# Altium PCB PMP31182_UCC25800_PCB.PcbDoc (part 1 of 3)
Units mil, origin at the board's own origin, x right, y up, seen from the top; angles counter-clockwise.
Board outline 4922 x 2266 mil, 4 copper layers (Top Layer, Signal Layer 1, Signal Layer 2, Bottom Layer), stack 77.9 mil thick; 172 components, 94 nets, 533 pads, 516 vias.
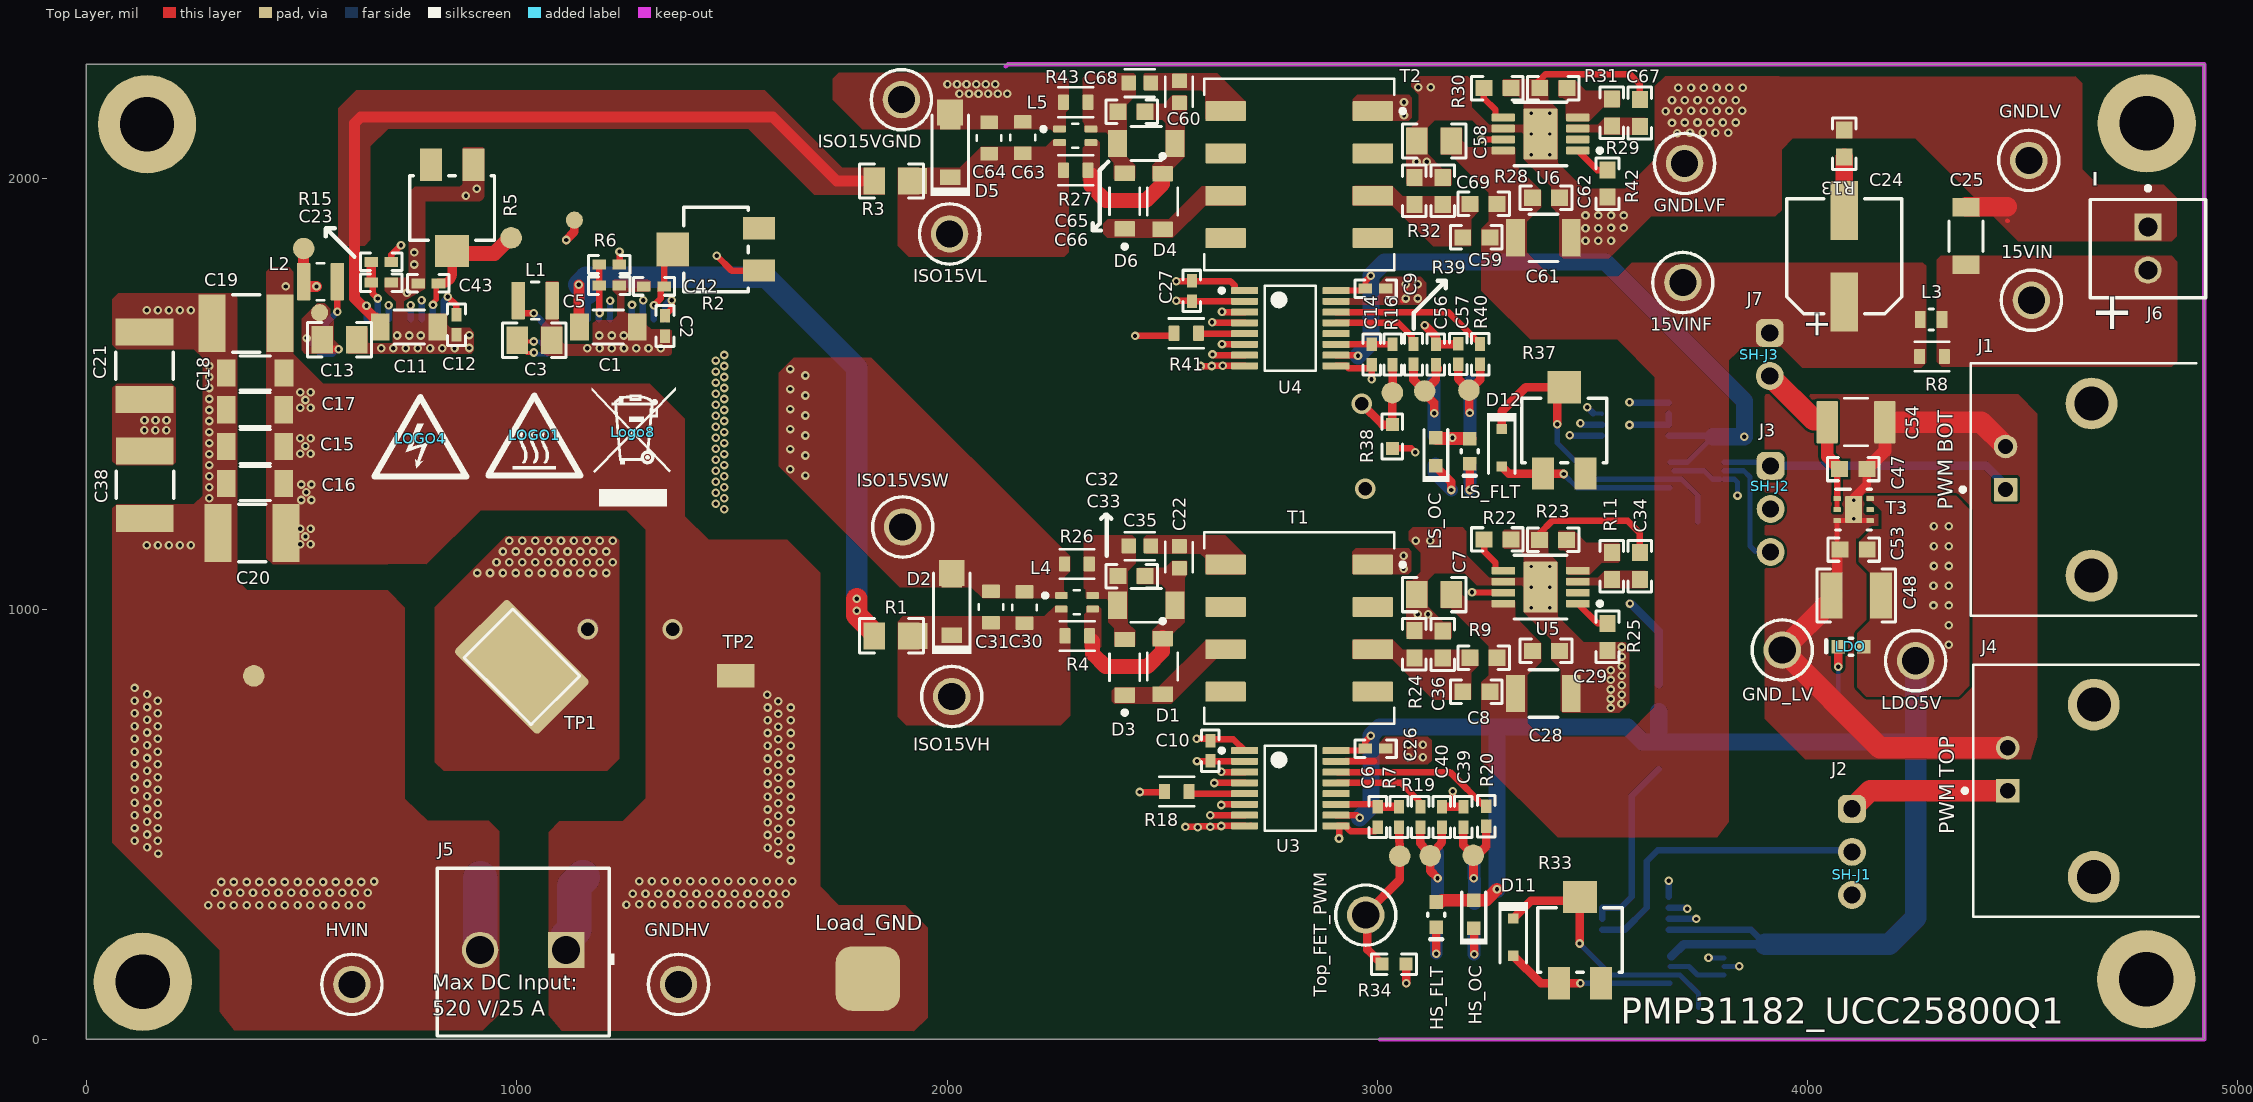
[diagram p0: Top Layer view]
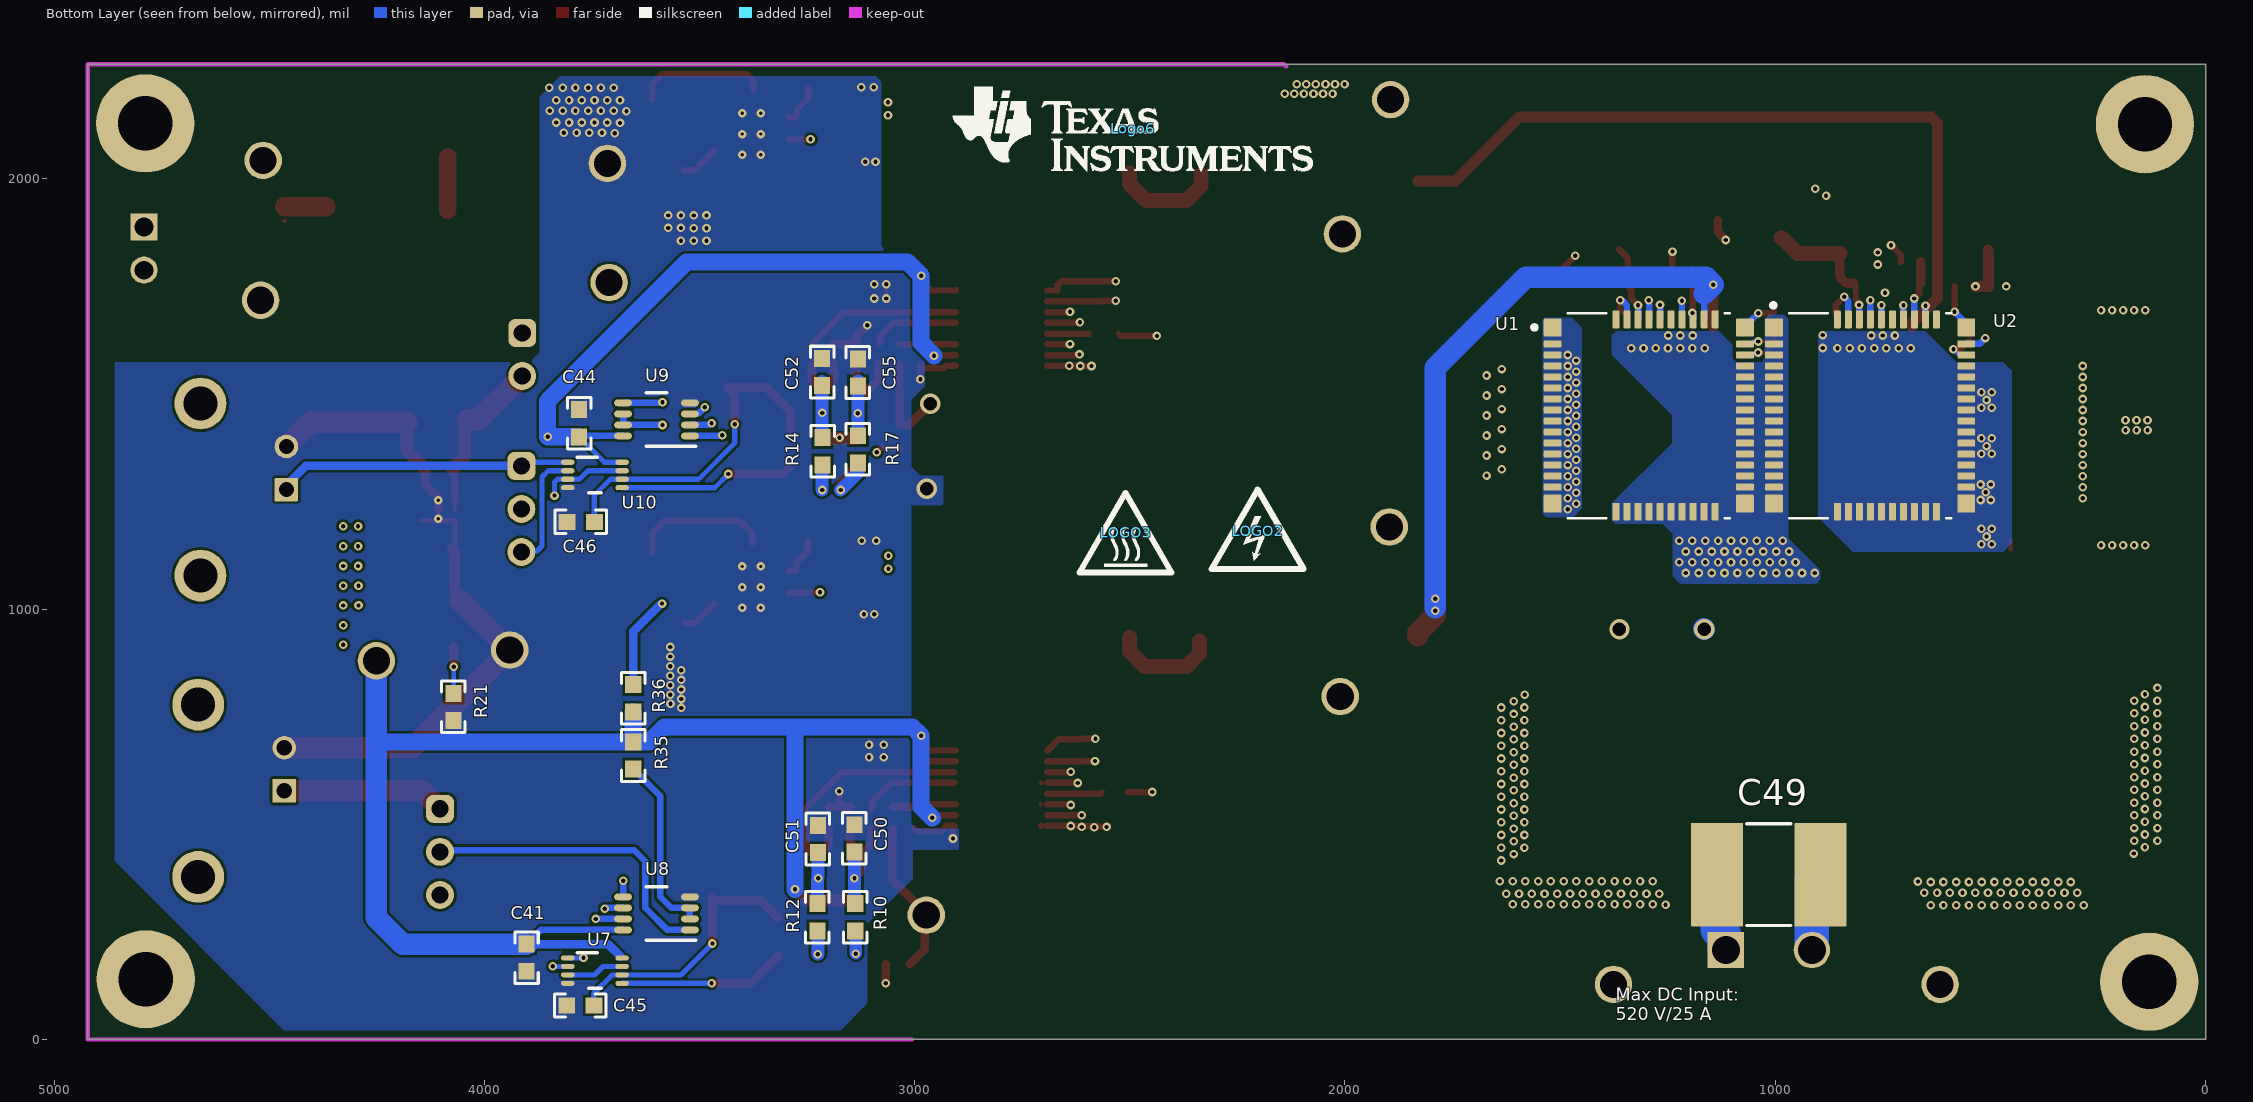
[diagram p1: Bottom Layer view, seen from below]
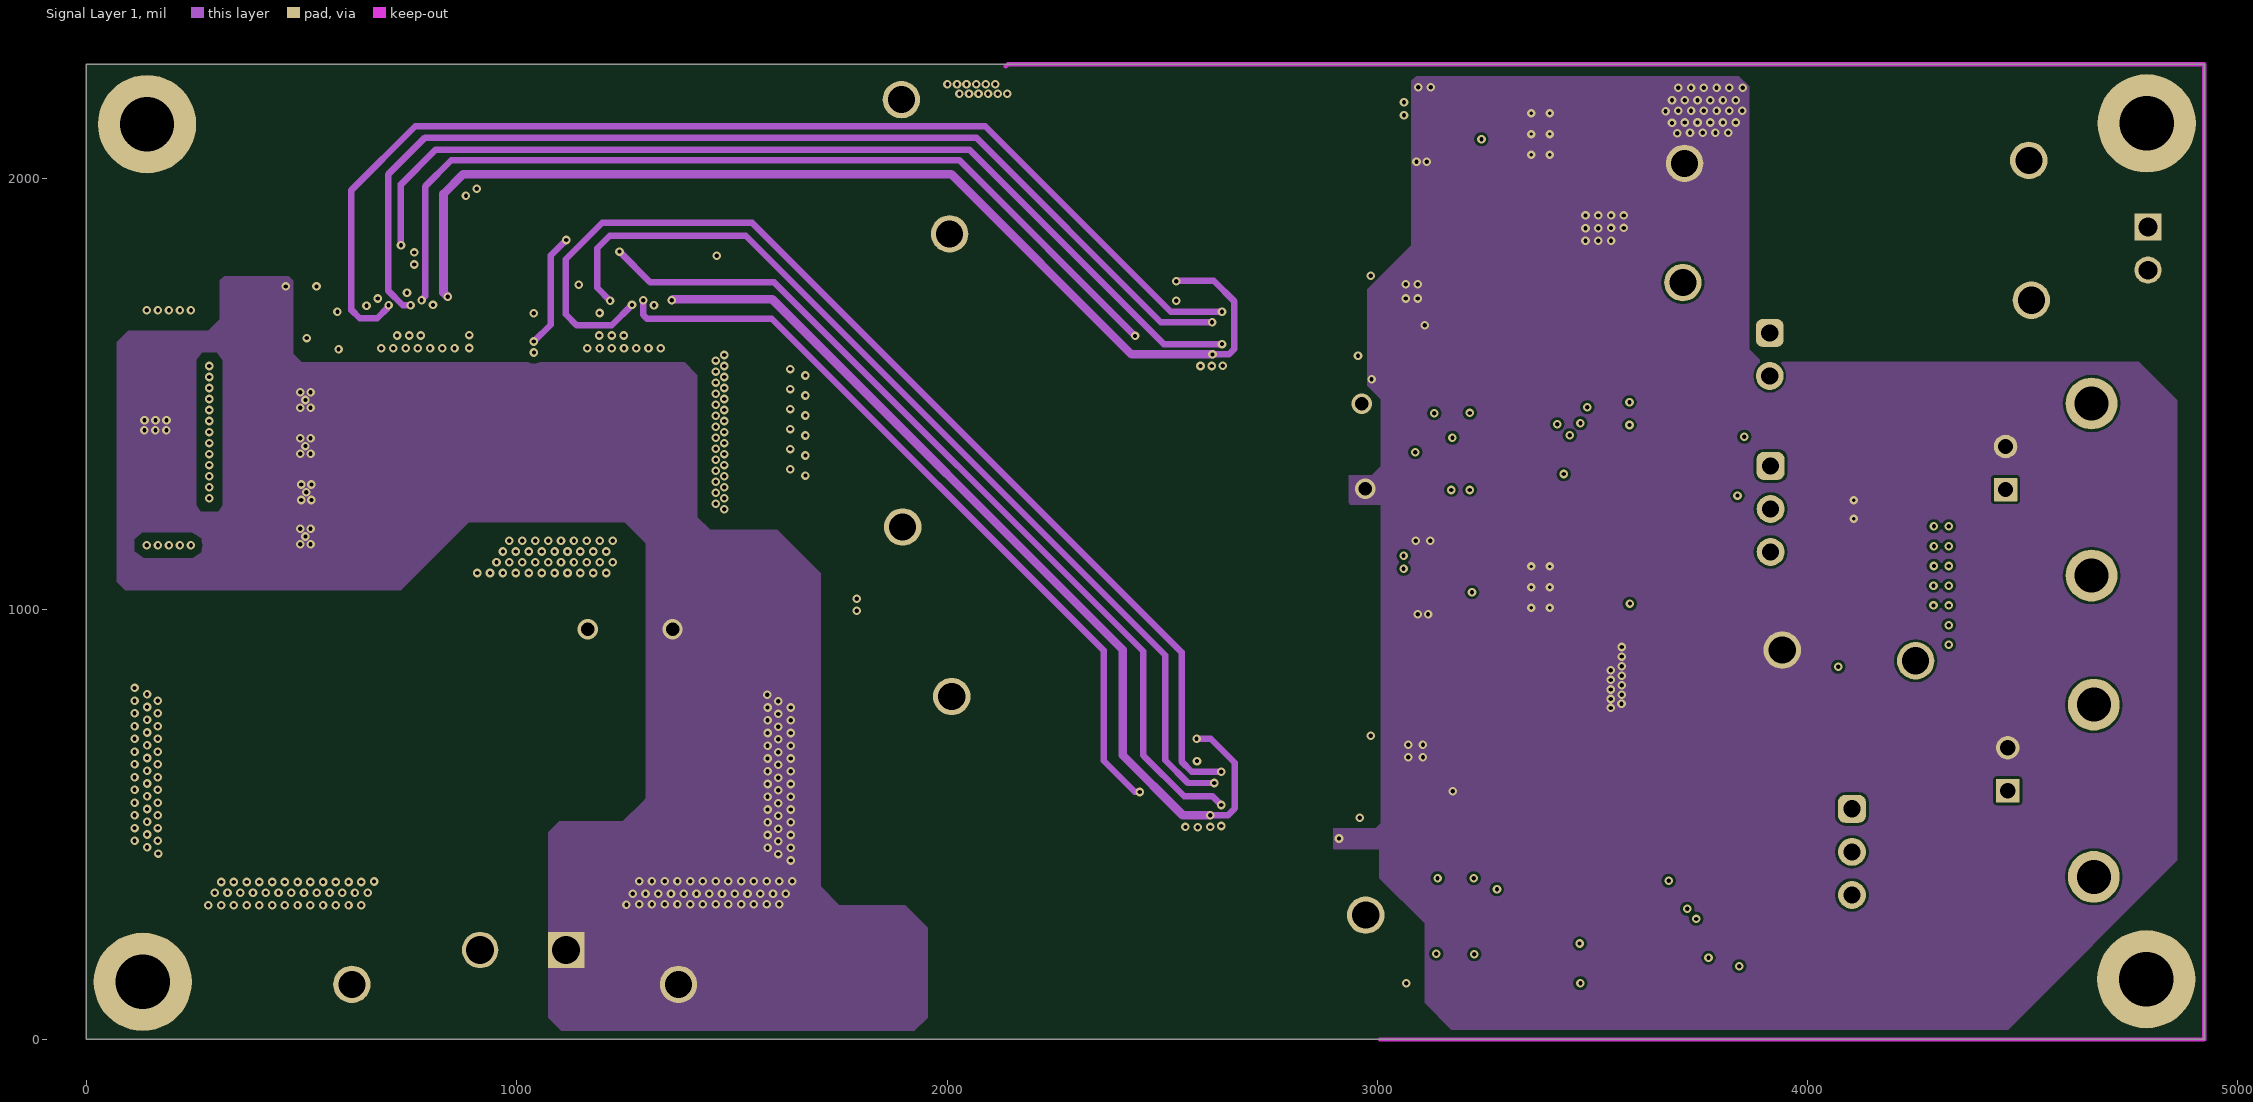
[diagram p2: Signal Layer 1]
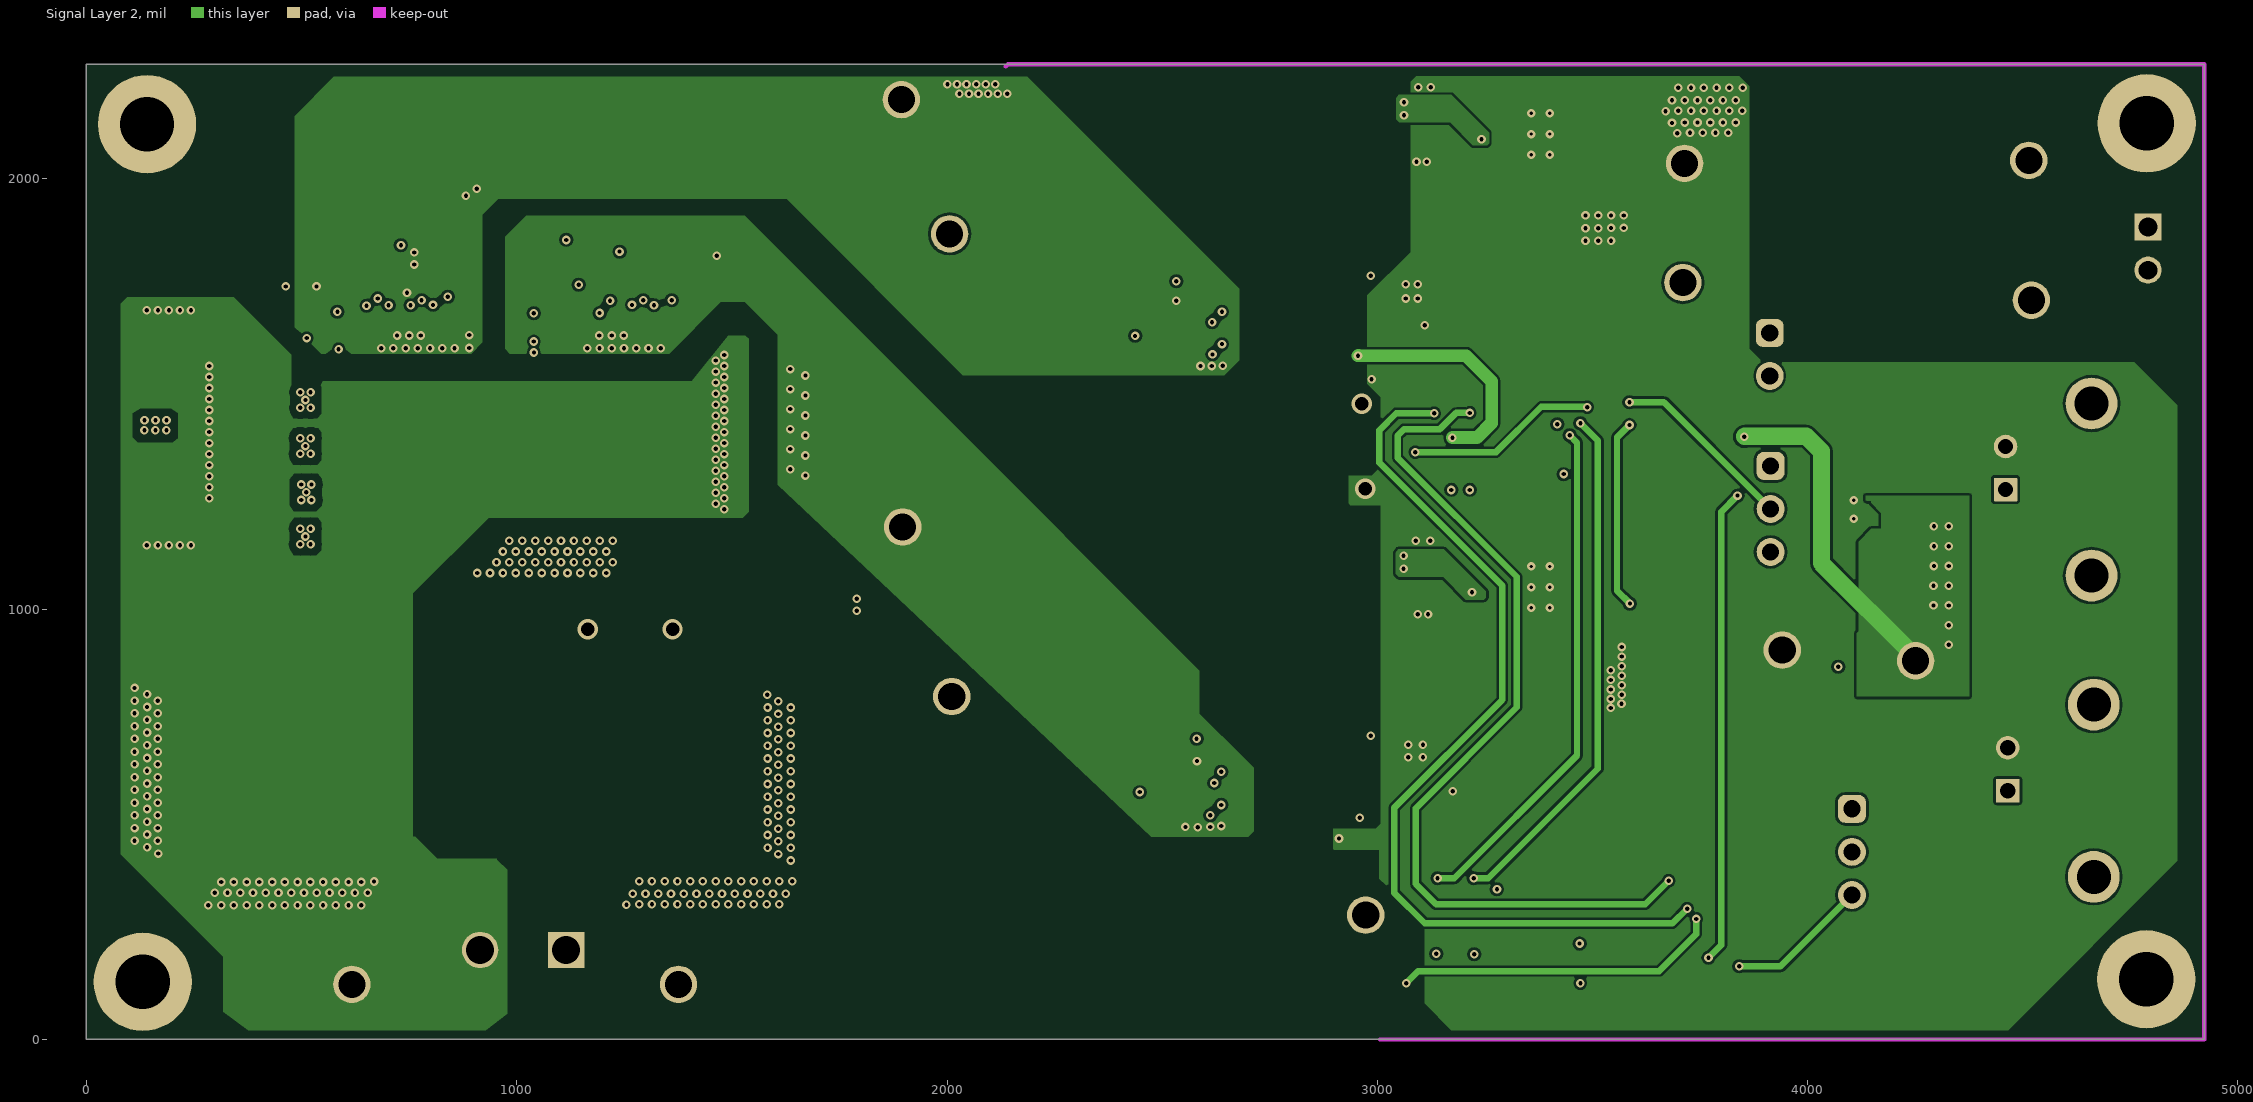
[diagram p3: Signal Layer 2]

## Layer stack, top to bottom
Top Solder: solder mask 0.4, Solder Resist, Dk 3.5
Top Layer: signal copper 2.8
Dielectric 1: prepreg 4.6, FR-4, Dk 4.2
Signal Layer 1: signal copper 2.8
Dielectric 2: core 57.5, FR-4, Dk 4.2
Signal Layer 2: signal copper 2.8
Dielectric 3: prepreg 4.6, FR-4, Dk 4.2
Bottom Layer: signal copper 2.8
Bottom Solder: solder mask 0.4, Solder Resist, Dk 3.5

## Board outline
0,2266 4922,2266 4922,0 0,0

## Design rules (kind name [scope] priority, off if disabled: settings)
AcuteAngle [All] p1: minimum=4.50000000000000E+0001 checktracksonly=FALSE
AssemblyTestPointUsage [All] p1: valid=2
BoardOutlineClearance [OnCopper] p1: gap=15 ignorepadtopadclearanceinfootprint=FALSE
Clearance "Clearance_Thermal Vias" [InNet('NC5')] p1: gap=20 ignorepadtopadclearanceinfootprint=FALSE
Clearance "Clearance_Thermal Vias_1" [InNet('NC6')] p2: gap=20 ignorepadtopadclearanceinfootprint=FALSE
Clearance Clearance_VSW_Mid1 [(OnMultiLayer Or OnMid) And InNetClass('VSWNET') vs OnMid And Not InNetClass('VSWNET')] p3: gap=16 ignorepadtopadclearanceinfootprint=TRUE
Clearance Clearance_Screw_Top [InNetClass('Screw') vs OnLayer('Top Layer') And Not InNetClass('Screw')] p4: gap=60 ignorepadtopadclearanceinfootprint=TRUE
Clearance Clearance_Screw_Bottom [InNetClass('Screw') vs OnLayer('Bottom Layer') And Not InNetClass('Screw')] p5: gap=60 ignorepadtopadclearanceinfootprint=TRUE
Clearance Clearance_Screw_Other [InNetClass('Screw') vs Not OnLayer('Top Layer')  AND Not InNetClass('Screw')] p6: gap=60 ignorepadtopadclearanceinfootprint=TRUE
Clearance Clearance_VSW_Mid2 [(OnMultiLayer Or OnMid) And Not InNetClass('VSWNET') vs OnMid And InNetClass('VSWNET')] p7: gap=16 ignorepadtopadclearanceinfootprint=TRUE
Clearance Clearance_VSW [InNetClass('VSWNET') and OnCopper vs Not InNetClass('VSWNET') and OnCopper] p8 off: gap=60 ignorepadtopadclearanceinfootprint=TRUE
Clearance Clearance_VHV_Mid1 [(OnMultiLayer Or OnMid) And InNetClass('VHV') vs OnMid And Not InNetClass('VHV')] p9: gap=16 ignorepadtopadclearanceinfootprint=TRUE
Clearance Clearance_VHV_Mid2 [(OnMultiLayer Or OnMid) And Not InNetClass('VHV') vs OnMid And InNetClass('VHV')] p10: gap=16 ignorepadtopadclearanceinfootprint=TRUE
Clearance Clearance_VHV [InNetClass('VHV') vs Not InNetClass('VHV')] p11: gap=60 ignorepadtopadclearanceinfootprint=FALSE
Clearance Clearance_INGND [InNetClass('INGND') and OnCopper vs Not InNetClass('INGND')  and OnCopper] p12: gap=60 ignorepadtopadclearanceinfootprint=FALSE
Clearance Clearance_Poly [All] p13: gap=6 ignorepadtopadclearanceinfootprint=FALSE
Clearance Clearance_1 [All] p14: gap=6 ignorepadtopadclearanceinfootprint=FALSE
ComponentClearance ComponentClearance_Shunt [InComponentClass('Header') vs InComponentClass('Shunt')] p1: gap=0 collisioncheckmode=3 verticalgap=0 showdistances=FALSE
ComponentClearance ComponentClearance_MountingHoles_FiducialMarks [InComponentClass('Mounting Holes') vs InComponentClass('FiducialMark')] p2 off: gap=50 collisioncheckmode=3 verticalgap=10 showdistances=FALSE
ComponentClearance ComponentClearance_Logo [InComponentClass('Logo')] p3: gap=0 collisioncheckmode=3 verticalgap=10 showdistances=FALSE
ComponentClearance ComponentClearance_ScrewToNut [(HasFootprint('NY PMS 440 0025 PH')) vs (HasFootprint('Keystone_1902C'))] p4: gap=5 collisioncheckmode=3 verticalgap=10 showdistances=FALSE
ComponentClearance ComponentClearance_MountingHoles [InComponentClass('Mounting Holes')] p5: gap=250 collisioncheckmode=3 verticalgap=100000 showdistances=FALSE
ComponentClearance ComponentClearance_SmallPassives [HasFootprint('0201*') or HasFootprint('0402*') or HasFootprint('0508') or HasFootprint('0603*') or HasFootprint('0612') or HasFootprint('0805*') or HasFootprint('0815*') or HasFootprint('0830*') or HasFootprint('1206*') or HasFootprint('1210*') or HasFootprint('1808*') or HasFootprint('1812*') or HasFootprint('1825*') or HasFootprint('2010*') or HasFootprint('2220*') or HasFootprint('2225*') or HasFootprint('2512*') or HasFootprint('2728*') or HasFootprint('3518*') vs HasFootprint('0201*') or HasFootprint('0402*') or HasFootprint('0508') or HasFootprint('0603*') or HasFootprint('0612') or HasFootprint('0805*') or HasFootprint('0815*') or HasFootprint('0830*') or HasFootprint('1206*') or HasFootprint('1210*') or HasFootprint('1808*') or HasFootprint('1812*') or HasFootprint('1825*') or HasFootprint('2010*') or HasFootprint('2220*') or HasFootprint('2225*') or HasFootprint('2512*') or HasFootprint('2728*') or HasFootprint('3518*')] p6: gap=9.84 collisioncheckmode=3 verticalgap=10 showdistances=FALSE
ComponentClearance ComponentClearance_THtoSMT [IsThruComponent vs IsSMTComponent] p7: gap=10 collisioncheckmode=3 verticalgap=30 showdistances=FALSE
ComponentClearance ComponentClearance_THtoTH [IsThruComponent vs IsThruComponent] p8: gap=74 collisioncheckmode=3 verticalgap=30 showdistances=FALSE
ComponentClearance [All] p9: gap=1 collisioncheckmode=3 verticalgap=10 showdistances=FALSE
DiffPairsRouting [All] p1: maxlimit=100 minlimit=10 mostfreqgap=10 toplayer_minwidth=15 toplayer_maxwidth=15 toplayer_prefwidth=15 midlayer1_minwidth=15 midlayer1_maxwidth=15 midlayer1_prefwidth=15 midlayer2_minwidth=15 midlayer2_maxwidth=15 midlayer2_prefwidth=15 bottomlayer_minwidth=15 bottomlayer_maxwidth=15 bottomlayer_prefwidth=15 maxuncoupledlength=1000
FabricationTestPointUsage TestPointUsage [All] p1: valid=2 allowmultiple=FALSE
FabricationTestpoint Testpoint [All] p1: side=3 testpointundercomponent=TRUE minsize=40 maxsize=100 preferedsize=60 minholesize=0 maxholesize=40 preferedholesize=32 testpointgrid=1 allowsidetop=TRUE allowsidebottom=TRUE usegrid=TRUE gridtolerance=0.01
FanoutControl Fanout_LCC [IsLCC] p1: bgadir=Out bgaviamode=Centered fanoutstyle=Auto fanoutdirection=Alternating viagrid=1 // Fanout_LCC (Default Rule)
FanoutControl Fanout_BGA [IsBGA] p2: bgadir=Out bgaviamode=Centered fanoutstyle=Auto fanoutdirection=Alternating viagrid=1 // Fanout_BGA (Default Rule)
FanoutControl Fanout_Default [All] p4: bgadir=Out bgaviamode=Centered fanoutstyle=Auto fanoutdirection=Alternating viagrid=1 // Fanout_Default (Default Rule)
FanoutControl Fanout_Small [(CompPinCount < 5)] p5: bgadir=Out bgaviamode=Centered fanoutstyle=Auto fanoutdirection=OutThenIn viagrid=1 // Fanout_Small (Default Rule)
HoleSize [All] p1: absolutevalues=TRUE maxlimit=251 minlimit=6 maxpercent=80.000 minpercent=20.000
MinimumAnnularRing MinimumAnnularRing_ThermalPadVias [IsVia and InAnyComponent] p1: minimumring=4.5
MinimumAnnularRing [IsVia] p2: minimumring=4.5
MinimumSolderMaskSliver MinimumSolderMaskSliver_Logo [InComponentClass('Logo') vs InComponentClass('Logo')] p1: minsoldermaskwidth=0.7
MinimumSolderMaskSliver [All] p2: minsoldermaskwidth=3.94
PlaneConnect [All] p1: planeconnectstyle=Relief reliefexpansion=10 reliefentries=4 reliefconductorwidth=10 reliefairgap=10
PolygonConnect [All] p1: connectstyle=Direct reliefconductorwidth=10 reliefentries=4 polygonreliefangle="90 Angle" airgapwidth=10
RoutingVias ThermalPadVias [IsVia and InAnyComponent] p1: holewidth=7.87 width=19.68 viastyle="Through Hole" minholewidth=7.87 minwidth=19.68 maxholewidth=12.99 maxwidth=23.62
RoutingVias [All] p2: holewidth=10 width=20 viastyle="Through Hole" minholewidth=6 minwidth=10 maxholewidth=40 maxwidth=65
SMDToCorner [All] p1: distance=30000
SilkToSilkClearance [All] p1: silktosilkclearance=0
SilkToSolderMaskClearance SilkscreenOverComponentPads [IsPad] p1: minsilkscreentomaskgap=5 clearancetoexposedcopper=TRUE
SolderMaskExpansion [All] p1: expansion=1.97 istentingtop=FALSE
Width [All] p1: maxlimit=1000 minlimit=6 preferedwidth=10 checkconnectedcopper=TRUE
16 further rules are at their usual default settings.

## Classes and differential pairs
component class Shunt: SH-J1 SH-J2 SH-J3
component class PMP31182_UCC25800_PWM: C41 C44 C45 C46 C47 C48 C49 C50 C51 C52 C53 C54 C55 D11 D12 GND_LV GNDHV HS_FLT HS_OC HVIN J1 J2 J3 J4 J5 J7 LDO LDO5V LS_FLT LS_OC R10 R12 R14 R17 R21 R33 R34 R35 R36 R37 R38 SH-J1 SH-J2 SH-J3 T3 Top_FET_PWM U7 U8 U9 U10
component class PMP31182_UCC25800_power_supply: 15VIN 15VINF C7 C8 C22 C24 C25 C28 C29 C30 C31 C32 C33 C34 C35 C36 C58 C59 C60 C61 C62 C63 C64 C65 C66 C67 C68 C69 D1 D2 D3 D4 D5 D6 D7 GNDLV GNDLVF ISO15VGND ISO15VH ISO15VL ISO15VSW J6 L3 L4 L5 R4 R8 R9 R11 R13 R22 R23 R24 R25 R26 R27 R28 R29 R30 R31 R32 R42 R43 T1 T2 U5 U6
component class Logo: Logo6
component class Header: J2 J3 J7
net class PGND: 5V_L FAULT_L GND_HV IN_L ISO_15V_L ISO_15V_L_B ISO_RET_L_B NC_PGND1 NC_PGND2 NC_PGND3 NetC11_2 NetC43_2 NetC60_1 NetD4_2 NetL2_2 NetR15_1 NetR41_2 OC_L TEMP_L VNEG_L
component class PMP31182_UCC25800_Hardware: !PCB1 FID2 H3 H4 H5 H6 LOGO1 LOGO2 LOGO3 LOGO4 Logo6 Logo8
component class PMP31182_UCC25800_GaN: C1 C2 C3 C5 C6 C9 C10 C11 C12 C13 C14 C15 C16 C17 C18 C19 C20 C21 C23 C26 C27 C38 C39 C40 C42 C43 C56 C57 L1 L2 R1 R2 R3 R5 R6 R7 R15 R16 R18 R19 R20 R39 R40 R41 TP1 TP2 U1 U2 U3 U4
net class VSWNET: 5V_H FAULT_H IN_H ISO_15V_H ISO_15V_H_B ISO_RET_H_B NC_SW1 NC_SW2 NC_SW3 NetC1_1 NetC22_1 NetC42_1 NetD1_2 NetL1_2 NetR6_1 NetR18_1 OC_H SW TEMP_H VNEG_H
net class VHV: HVBUS

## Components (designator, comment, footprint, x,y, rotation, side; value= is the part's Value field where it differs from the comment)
15VIN "5005" Keystone5005 4520,1718 r180 top
15VINF "5005" Keystone5005 3710,1759 r180 top
C1 "TMK316AB7106KLHT" 1206_180 1213,1656 r0 top value=10uF
C2 "GCM155R71C224KE02D" 0402 1344.59,1658 r270 top value=0.22uF
C3 "CGA4J3X7R1E225K125AB" 0805_HV 1041,1625 r180 top value=2.2uF
C5 "GCM1555C1H220JA16D" 0402 1215,1752 r180 top value=22pF
C6 "C1005C0G1H680J050BA" 0402 3001,517.12 r270 top value=68pF
C7 "C2012X7R1H225K125AC" 0805_HV 3132,1034 r180 top value=2.2uF
C8 "GRM188C71E225KE11D" 0603 3230,808 r180 top value=2.2uF
C9 "GRT155R6YA105KE13D" 0402 2996,1744.81 r0 top value=1uF
C10 "GCM155R71H104KE02D" 0402 2612,671 r270 top value=0.1uF
C11 "TMK316AB7106KLHT" 1206_180 749.96,1656 r180 top value=10uF
C12 "GCM155R71C224KE02D" 0402 860,1661 r270 top value=0.22uF
C13 "CGA4J3X7R1E225K125AB" 0805_HV 588,1626 r180 top value=2.2uF
C14 "C1005C0G1H680J050BA" 0402 2987,1591.88 r90 top value=68pF
C15 "C1206C223KDRACTU" 1206_190 392,1378 r0 top value=0.022uF
C16 "C1206C223KDRACTU" 1206_190 392,1292 r0 top value=0.022uF
C17 "C1206C223KDRACTU" 1206_190 391.87,1463.49 r0 top value=0.022uF
C18 "C1206C223KDRACTU" 1206_190 392.15,1549.1 r0 top value=0.022uF
C19 "C1812W104KDRACTU" 1812_254 371,1664 r0 top value=0.1uF
C20 "C1812W104KDRACTU" 1812_254 385,1177 r0 top value=0.1uF
C21 "C1812W104KDRACTU" 1812_254 135,1565.74 r270 top value=0.1uF
C22 "C0603X563K5RACAUTO" FP-C0603X563K5RACAUTO_0603-MFG 2540,1120.59 r270 top value=56nF
C23 "GCM1555C1H220JA16D" 0402 685.1,1758.91 r180 top value=22pF
C24 "HHXC250ARA470MF61G" HXB_F61 4085,1820 r90 top value=47uF
C25 "C1206C106J3RACAUTO" 1206_180 4368,1867 r90 top value=10uF
C26 "GRT155R6YA105KE13D" 0402 2996,676 r0 top value=1uF
C27 "GCM155R71H104KE02D" 0402 2569,1739.62 r270 top value=0.1uF
C28 "CGA6P3X7R1H475M250AB" 1210_280 3386,804 r0 top value=4.7uF
C29 "CGA3E3X8R1H104K080AE" 0603 3392,903 r0 top value=0.1uF
C30 "CGA4J1X7S1E106K125AC" FP-CGA4J1X7S1E106K125AC_0805-MFG 2180,1004 r90 top value=10µF
C31 "CGA4J1X7S1E106K125AC" FP-CGA4J1X7S1E106K125AC_0805-MFG 2102,1005 r90 top value=10µF
C32 "CGA3E3X8R1H104K080AE" 0603 2429,1077 r180 top value=0.1uF
C33 "CGA5L1X7R1H106K160AC" 1206_190 2463,1009 r180 top value=10uF
C34 "CGA3E3X5R1H105M080AB" 0603 3610,1100 r90 top value=1uF
C35 "C0603X563K5RACAUTO" FP-C0603X563K5RACAUTO_0603-MFG 2448,1147 r0 top value=56nF
C36 "GRM188C71E225KE11D" 0603 3152,918 r90 top value=2.2uF
C38 "C1812W104KDRACTU" 1812_254 136,1289 r90 top value=0.1uF
C39 "GCQ1555C1H430JB01D" 0402 3200,517 r90 top value=43pF
C40 "GCQ1555C1H430JB01D" 0402 3150,517 r90 top value=43pF
C41 "CGA3E1X7R1E105K080AD" 0603 3902,190 r90 bottom value=1uF
C42 "CGA2B2C0G1H101J050BA" 0402 1319,1750 r180 top value=100pF
C43 "CGA2B2C0G1H101J050BA" 0402 794.62,1757 r0 top value=100pF
C44 "CGA3E1X7R1E105K080AD" 0603 3780,1432 r270 bottom value=1uF
C45 "GRM1885C1H390JA01D" 0603 3777,79 r0 bottom value=39pF
C46 "GRM1885C1H390JA01D" 0603 3776,1203 r0 bottom value=39pF
C47 "CGA3E3X8R1H104K080AE" 0603 4106,1325.63 r0 top value=0.1uF
C48 "GRT32ER61E226KE13L" 1210_270 4113,1031.63 r180 top value=22uF
C49 "2220Y6300105KETWS2" 2220_450 1015,383 r0 bottom value=1uF
C50 "GRM1885C1H390JA01D" 0603 3140,467.5 r90 bottom value=39pF
C51 "GRM1885C1H390JA01D" 0603 3225,466 r90 bottom value=39pF
C52 "GRM1885C1H390JA01D" 0603 3214.93,1551 r90 bottom value=39pF
C53 "CGA3E3X8R1H104K080AE" 0603 4107,1138.63 r180 top value=0.1uF
C54 "UMK325AB7106KMHP" FP-UMK325AB7106KMHP_1210-MFG 4112.43,1434.63 r180 top value=10µF
C55 "GRM1885C1H390JA01D" 0603 3131.93,1550 r90 bottom value=39pF
C56 "GCQ1555C1H430JB01D" 0402 3136,1592 r90 top value=43pF
C57 "GCQ1555C1H430JB01D" 0402 3188,1593 r90 top value=43pF
C58 "C2012X7R1H225K125AC" 0805_HV 3132,2088 r180 top value=2.2uF
C59 "GRM188C71E225KE11D" 0603 3230,1864 r180 top value=2.2uF
C60 "C0603X563K5RACAUTO" FP-C0603X563K5RACAUTO_0603-MFG 2540,2202 r270 top value=56nF
C61 "CGA6P3X7R1H475M250AB" 1210_280 3386,1863 r0 top value=4.7uF
C62 "CGA3E3X8R1H104K080AE" 0603 3392,1956 r0 top value=0.1uF
C63 "CGA4J1X7S1E106K125AC" FP-CGA4J1X7S1E106K125AC_0805-MFG 2176,2096 r90 top value=10µF
C64 "CGA4J1X7S1E106K125AC" FP-CGA4J1X7S1E106K125AC_0805-MFG 2098,2095 r90 top value=10µF
C65 "CGA3E3X8R1H104K080AE" 0603 2429,2156 r180 top value=0.1uF
C66 "CGA5L1X7R1H106K160AC" 1206_190 2463,2082 r180 top value=10uF
C67 "CGA3E3X5R1H105M080AB" 0603 3610,2153 r90 top value=1uF
C68 "C0603X563K5RACAUTO" FP-C0603X563K5RACAUTO_0603-MFG 2448,2223 r0 top value=56nF
C69 "GRM188C71E225KE11D" 0603 3152,1972 r90 top value=2.2uF
D1 "NRVB0540T1G" FP-NRVB0540T1G_SOD-123-MFG 2501,867 r270 top
D2 "BZT52C18-7-F" SOD-123 2011,1004 r90 top value=18V
D3 "NRVB0540T1G" FP-NRVB0540T1G_SOD-123-MFG 2413,865 r90 top
D4 "NRVB0540T1G" FP-NRVB0540T1G_SOD-123-MFG 2501,1947.46 r270 top
D5 "BZT52C18-7-F" SOD-123 2007.16,2068 r90 top value=18V
D6 "NRVB0540T1G" FP-NRVB0540T1G_SOD-123-MFG 2413,1948 r90 top
D11 "BAT42WS-7-F" SOD-323 3316,238 r270 top value=30V
D12 "BAT42WS-7-F" SOD-323 3289,1375 r270 top value=30V
GND_LV "5006" Keystone5006 3941,905 r180 top
GNDHV "5006" Keystone5006 1376,128 r180 top
GNDLV "5006" Keystone5006 4514,2043 r180 top
GNDLVF "5006" Keystone5006 3714,2036 r180 top
HS_FLT "LS L29K-G1J2-1-Z" "LS L29K_Red" 3137,290 r270 top value=Red
HS_OC "SML-E12Y8WT86" SML-E1_Yellow 3224,291 r90 top value=Yellow
HVIN "5005" Keystone5005 617,128 r0 top
ISO15VGND "5006" Keystone5006 1894,2184 r180 top
ISO15VH "5005" Keystone5005 2011,797 r180 top
ISO15VL "5005" Keystone5005 2006,1872 r180 top
ISO15VSW "5006" Keystone5006 1897,1191 r180 top
J1 "0731375003" FP-0731375003_CONN_BNC_RCPT-MFG 5074.57,1278 r90 top
J2 "TSW-103-07-G-S" TSW-103-07-G-S 4103,436 r270 top
J3 "TSW-103-07-G-S" TSW-103-07-G-S 3914,1233 r270 top
J4 "0731375003" FP-0731375003_CONN_BNC_RCPT-MFG 5079.57,578 r90 top
J5 "0395443002" Molex_0395443002 1015,208 r180 top
J6 "282834-2" TEC_282834-2 4791,1838 r270 top
J7 "TSW-102-07-G-S" TSW-102-07-G-S 3912,1592 r270 top
L1 "MPIA2510V2-4R7-R" FP-MPIA2510V2-4R7-R_1008-MFG 1043,1717 r180 top value=4.7uH
L2 "MPIA2510V2-4R7-R" FP-MPIA2510V2-4R7-R_1008-MFG 544,1761 r0 top value=4.7uH
L3 "0603PS-SRF Inductor" 0603AF 4287,1673 r180 top value=240nH
L4 "ACM2012-900-2P-T001" FP-ACM2012-900-2P-T001_SMD4-MFG 2302,1016 r0 top
L5 "ACM2012-900-2P-T001" FP-ACM2012-900-2P-T001_SMD4-MFG 2298,2100 r0 top
LDO "LS L29K-G1J2-1-Z" "LS L29K_Red" 4100.53,913 r180 top value=Red
LDO5V "5005" Keystone5005 4251,880 r180 top
LOGO1 "CAUTION HOT SURFACE" IEC_HotSurface_Small 1041,1404 r0 top
LOGO2 "DANGER HIGH VOLTAGE" IEC_HighVoltage_Small 2203,1181 r180 bottom
LOGO3 "CAUTION HOT SURFACE" IEC_HotSurface_Small 2510,1178 r180 bottom
LOGO4 "DANGER HIGH VOLTAGE" IEC_HighVoltage_Small 776,1396 r0 top
Logo6 "Texas Instruments" TI_Stacked_Overlay_Small 2493,2116 r180 bottom
Logo8 "WEEE logo" WEEE_Minimum 1270,1411 r0 top
LS_FLT "LS L29K-G1J2-1-Z" "LS L29K_Red" 3215,1367 r270 top value=Red
LS_OC "SML-E12Y8WT86" SML-E1_Yellow 3136,1366 r90 top value=Yellow
R1 "CRCW08050000Z0EAHP" 0805_HV 1871,938 r180 top value=0
R2 "3224X-1-204E" TRIM_3224X 1463,1836 r180 top value=200K
R3 "CRCW08050000Z0EAHP" 0805_HV 1871,1995 r180 top value=0
R4 "ERJ-3GEY0R00V" FP-ERJ-3GEY0R00V_0603-MFG 2303,938 r180 top
R5 "3224X-1-204E" TRIM_3224X 850,1932.39 r270 top value=200K
R6 "CRCW0402300RJNED" 0402 1215,1801 r180 top value=300
R7 "CRCW040249R9FKED" 0402 3050.5,517.12 r90 top value=49.9
R8 "ERJ-3GEY0R00V" FP-ERJ-3GEY0R00V_0603-MFG 4289,1587 r180 top
R9 "RT0603BRD07100KL" 0603 3247,887 r0 top value=100k
R10 "CRCW06033K30JNEA" 0603 3138,284 r270 bottom value=3.3k
R11 "RT0603BRD0724K9L" 0603 3545,1100 r270 top value=24.9k
R12 "CRCW06033K30JNEA" 0603 3226,284 r270 bottom value=3.3k
R13 "ERJ-3RQFR33V" 0603 4085,2082 r270 top value=0.33
R14 "CRCW06033K30JNEA" 0603 3214.07,1367 r270 bottom value=3.3k
R15 "CRCW0402300RJNED" 0402 685.1,1807 r180 top value=300
R16 "CRCW040249R9FKED" 0402 3035.5,1591.88 r90 top value=49.9
R17 "CRCW06033K30JNEA" 0603 3132,1371.5 r270 bottom value=3.3k
R18 "ERJ-3GEY0R00V" FP-ERJ-3GEY0R00V_0603-MFG 2534,576 r180 top
R19 "CRCW0402300RJNED" 0402 3100,517 r270 top value=300
R20 "CRCW0402300RJNED" 0402 3253,518.62 r270 top value=300
R21 "CRCW06033K30JNEA" 0603 4072,773 r90 bottom value=3.3k
R22 "RT0603BRD0730K1L" 0603 3279,1162 r180 top value=30.1k
R23 "RT0603DRE0722K9L" 0603 3408.5,1161 r0 top value=22.9k
R24 "RT0603BRD07100KL" 0603 3086,918.5 r270 top value=100k
R25 "RMCF0603ZT0R00" 0603 3535,935.5 r90 top value=0
R26 "ERJ-3GEY0R00V" FP-ERJ-3GEY0R00V_0603-MFG 2302,1105 r180 top
R27 "ERJ-3GEY0R00V" FP-ERJ-3GEY0R00V_0603-MFG 2299,2020 r180 top
R28 "RT0603BRD07100KL" 0603 3247,1942 r0 top value=100k
R29 "RT0603BRD0724K9L" 0603 3545,2154 r270 top value=24.9k
R30 "RT0603BRD0730K1L" 0603 3279,2211 r180 top value=30.1k
R31 "RT0603DRE0722K9L" 0603 3409,2210.93 r0 top value=22.9k
R32 "RT0603BRD07100KL" 0603 3086,1972 r270 top value=100k
R33 "3224X-1-502E" TRIM_3224X 3471,231 r90 top value=5K
R34 "CRCW06030000Z0EA" 0603_HV 3039,175 r180 top value=0
R35 "CRCW0603100KJNEAC" 0603 3654,660 r270 bottom value=100k
R36 "CRCW0603100KJNEAC" 0603 3654,793 r270 bottom value=100k
R37 "3224X-1-502E" TRIM_3224X 3434.5,1415.5 r90 top value=5K
R38 "CRCW06030000Z0EA" 0603_HV 3035,1401 r90 top value=0
R39 "CRCW0402300RJNED" 0402 3084,1592.62 r270 top value=300
R40 "CRCW0402300RJNED" 0402 3239,1592.62 r270 top value=300
R41 "ERJ-3GEY0R00V" FP-ERJ-3GEY0R00V_0603-MFG 2556,1641 r180 top
R42 "RMCF0603ZT0R00" 0603 3535,1989 r90 top value=0
R43 "ERJ-3GEY0R00V" FP-ERJ-3GEY0R00V_0603-MFG 2299,2178 r180 top
SH-J1 "SNT-100-BK-G" SNT-100-BK-G 4103,383 r270 top value=1x2
SH-J2 "SNT-100-BK-G" SNT-100-BK-G 3913,1286 r270 top value=1x2
SH-J3 "SNT-100-BK-G" SNT-100-BK-G 3888,1591 r90 top value=1x2
T1 "750319834-Q1" FP-750319177r02_SMT_11MM21_11MM3-MFG 2818.45,956 r180 top
T2 "750319834-Q1" FP-750319177r02_SMT_11MM21_11MM3-MFG 2818.45,2009.98 r180 top
T3 "TPS7B8150QDRVRQ1" DRV0006A 4107,1231.35 r0 top
Top_FET_PWM "5007" Keystone5007 2973,289 r90 top
TP1 "5016" Testpoint_Keystone_Compact 1012,866 r135 top
TP2 "S2751-46R" Harwin_S2751-46R 1509,845 r180 top
U1 "LMG3525R030Q" RQS0052A-MFG 1294,1449.98 r180 bottom
U2 "LMG3525R030Q" RQS0052A-MFG 779.58,1449.98 r180 bottom
U3 "ISO7741FQDBQRQ1" DBQ0016A-MFG 2797.78,584 r0 top
U4 "ISO7741FQDBQRQ1" DBQ0016A-MFG 2797.78,1653 r0 top
U5 "UCC25800DGNRQ1" DGN0008G-MFG 3379.39,1051.2 r180 top
U6 "UCC25800DGNRQ1" DGN0008G-MFG 3379.39,2104.2 r180 top
U7 "SN74LVC3G14DCUTG4" DCU0008A_N 3743.01,160 r180 bottom
U8 "SN74LVC2G08IDCTRQ1" DCT0008A_N 3600,293 r0 bottom
U9 "SN74LVC2G08IDCTRQ1" DCT0008A_N 3600,1441 r0 bottom
U10 "SN74LVC3G14DCUTG4" DCU0008A_N 3743.01,1311.84 r180 bottom

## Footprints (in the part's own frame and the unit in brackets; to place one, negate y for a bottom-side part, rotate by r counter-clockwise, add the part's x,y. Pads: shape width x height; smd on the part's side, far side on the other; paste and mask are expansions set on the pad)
0402 [mm] "0402 from SM-752 data"
  rect 0.8x0.6 smd: 1(-0.6,0) 2(0.6,0)
  silkscreen extent -1.22,-0.52 1.22,0.52, body extent -0.55,-0.3 0.55,0.3, height 0.6
0603 [mm] "0603 from SM-752 data"
  rect 1x0.95 smd: 1(-0.8,0) 2(0.8,0)
  silkscreen extent -1.52,-0.69 1.52,0.69, body extent -0.87,-0.47 0.87,0.47, height 1
0603_HV [mil] "Ernesto recommended land pattern.  26 mil between pads."
  rect 30x30 smd: 1(-28,0) 2(28,0)
  silkscreen extent -52,-24 52,24, body extent -34,-19 34,19, height 39
0603AF [mm] "COILCRAFT"
  rect 0.64x1.02 smd: 1(-0.64,0) 2(0.64,0)
  silkscreen extent -0.13,-0.63 0.13,0.63, body extent -0.92,-0.56 0.92,0.56, height 0.9
0805_HV [mil] "0805 with 30mil clearance between pads"
  rect 50x63 smd: 1(-40,0) 2(40,0)
  silkscreen extent -74,-40 74,40, body extent -43,-29 43,29, height 57
1206_180 [mm] "1206_180"
  rect 1.1x1.6 smd: 1(-1.7,0) 2(1.7,0)
  silkscreen extent -0.9,-1 0.9,1, body extent -1.75,-0.95 1.75,0.95, height 1.8
1206_190 [mm] "1206_190"
  rect 1.1x1.6 smd: 1(-1.7,0) 2(1.7,0)
  silkscreen extent -0.9,-1 0.9,1, body extent -1.75,-0.95 1.75,0.95, height 1.9
1210_270 [mm] "1210"
  rect 1.3x2.7 smd: 1(-1.45,0) 2(1.45,0)
  silkscreen extent -2.32,-1.57 2.32,1.57, body extent -1.7,-1.35 1.7,1.35, height 2.7
1210_280 [mm] "SMD, 2-Leads, Body 3.6x2.8mm, Height 2.8mm"
  rect 1.1x2.2 smd: 1(-1.65,0) 2(1.65,0)
  silkscreen extent -0.84,-1.4 0.84,1.4, body extent -1.8,-1.4 1.8,1.4, height 2.8
1812_254 [mm] "SMD, 2-Leads, Body 4.8x3.4mm"
  rect 1.6x3.4 smd: 1(-2,0) 2(2,0)
  silkscreen extent -0.8,-1.7 0.8,1.7, body extent -2.4,-1.7 2.4,1.7, height 2.54
2220_450 [mm] "Laird recommended land pattern"
  rrect3% 3.07x6.1 smd: 1(-3.06,0) 2(3.06,0)
  silkscreen extent -1.3,-3 1.3,3, body extent -2.8,-2.54 2.79,2.54, height 4.5
DBQ0016A-MFG [mm]
  rrect24% 1.6x0.41 smd paste+0 mask+0: 1(-2.7,2.222) 2(-2.7,1.587) 3(-2.7,0.953) 4(-2.7,0.318) 5(-2.7,-0.318) 6(-2.7,-0.953) 7(-2.7,-1.588) 8(-2.7,-2.223) 9(2.7,-2.223) 10(2.7,-1.588) 11(2.7,-0.953) 12(2.7,-0.318) 13(2.7,0.318) 14(2.7,0.953) 15(2.7,1.587) 16(2.7,2.222)
  silkscreen extent -4.17,-2.5 1.5,2.5, body extent -3.6,-2.75 3.6,2.75, height 0.25
DCT0008A_N [mm] "TSOP, 8-Leads, Body 3x2.8mm, Pitch 0.65mm, IPC Medium Density"
  oval 1.05x0.4 smd: 1(-1.975,0.975) 2(-1.975,0.325) 3(-1.975,-0.325) 4(-1.975,-0.975) 5(1.975,-0.975) 6(1.975,-0.325) 7(1.975,0.325) 8(1.975,0.975)
  silkscreen extent -2.32,-1.57 0.6,1.58, body extent -2.01,-1.47 2.01,1.48, height 1.3
DCU0008A_N [mm] "TSSOP, 8-Leads, Body 2x2.3mm, Pitch 0.5mm, IPC Medium Density"
  oval 0.8x0.3 smd: 1(-1.6,0.75) 2(-1.6,0.25) 3(-1.6,-0.25) 4(-1.6,-0.75) 5(1.6,-0.75) 6(1.6,-0.25) 7(1.6,0.25) 8(1.6,0.75)
  silkscreen extent -1.05,-1.05 0.38,1.05, body extent -1.56,-1 1.56,1, height 0.9
DGN0008G-MFG [mm]
  rrect22% 1.4x0.45 smd paste+0 mask+0: 1(-2.2,0.975) 2(-2.2,0.325) 3(-2.2,-0.325) 4(-2.2,-0.975) 5(2.2,-0.975) 6(2.2,-0.325) 7(2.2,0.325) 8(2.2,0.975)
  rrect5% 2x3 smd paste-1000 mask-1000: 9(0,0)
  silkscreen extent -3.63,-1.88 1.55,1.88, body extent -3,-1.8 3,1.8, height 0.25
DRV0006A [mm] "SON, 6-Leads, Body 2x2mm, Pitch 0.65mm, Thermal Pad 1.6x1mm, TI Recommended"
  rrect33% 0.45x0.3 smd: 1(-0.975,0.65) 2(-0.975,0) 3(-0.975,-0.65) 4(0.975,-0.65) 5(0.975,0) 6(0.975,0.65)
  rrect14% 1x0.7 on Top Paste: 7(0,-0.45) 7(0,0.45)
  rrect10% 1x1.6 smd paste-0.5: 7(0,0)
  silkscreen extent -1.05,-1.2 1.05,1.2, body extent -1.05,-1.05 1.05,1.05, height 0.81
FP-0731375003_CONN_BNC_RCPT-MFG [mm]
  rrect7% 1.39x1.39 hole 0.89 paste-1000 mask+0: 1(0,15.61)
  round 1.39 hole 0.89 paste-1000 mask+0: 2(2.54,15.61)
  round 3.06 hole 2.01 paste-1000 mask+0: 3(-5.08,10.53) 4(5.08,10.53)
  silkscreen extent -7.44,4.35 7.44,18.26, body extent -7.54,-17.75 7.54,17.75, height 0.25
FP-750319177r02_SMT_11MM21_11MM3-MFG [mm]
  rrect9% 2.39x1.17 smd paste+0 mask+0: 1(-4.345,-3.75) 2(-4.345,-1.25) 3(-4.345,1.25) 4(-4.345,3.75) 5(4.345,3.75) 6(4.345,1.25) 7(4.345,-1.25) 8(4.345,-3.75)
  silkscreen extent -6.23,-5.65 5.61,5.65, body extent -5.71,-5.75 5.71,5.75, height 0.25
FP-ACM2012-900-2P-T001_SMD4-MFG [mm]
  rrect25% 0.75x0.4 smd paste+0 mask+0: 1(-0.925,0.4) 2(-0.925,-0.4) 3(0.925,-0.4) 4(0.925,0.4)
  silkscreen extent -2,-0.7 0.18,0.7, body extent -1.4,-0.8 1.4,0.8, height 0.25
FP-C0603X563K5RACAUTO_0603-MFG [mm]
  rrect12% 0.85x0.9 smd paste+0 mask+0: 1(-0.65,0) 2(0.65,0)
  silkscreen extent -0.9,-0.83 0.87,0.8, body extent -1.2,-0.6 1.2,0.6, height 0.25
FP-CGA4J1X7S1E106K125AC_0805-MFG [mm]
  rrect13% 0.8x1.05 smd paste+0 mask+0: 1(-0.925,0) 2(0.925,0)
  silkscreen extent -0.15,-0.72 0.15,0.72, body extent -1.43,-0.82 1.43,0.82, height 0.25
FP-ERJ-3GEY0R00V_0603-MFG [mm]
  rrect15% 0.65x0.9 smd paste+0 mask+0: 1(-0.725,0) 2(0.725,0)
  silkscreen extent -1.03,-0.87 1.03,0.87, body extent -1.15,-0.58 1.15,0.58, height 0.25
FP-MPIA2510V2-4R7-R_1008-MFG [mm]
  rrect13% 0.8x2.2 smd paste+0 mask+0: 1(-1,0) 2(1,0)
  silkscreen extent -0.23,-1.1 0.23,1.1, body extent -1.5,-1.2 1.5,1.2, height 0.25
FP-NRVB0540T1G_SOD-123-MFG [mil]
  rrect11% 36x48 smd paste+0 mask+0: 1(-64.5,0) 2(64.5,0)
  silkscreen extent -110,-35 32,35, body extent -86,-39 86,39, height 10
FP-UMK325AB7106KMHP_1210-MFG [mm]
  rrect8% 1.25x2.5 smd paste+0 mask+0: 1(-1.7,0) 2(1.7,0)
  silkscreen extent -0.7,-1.4 0.7,1.4, body extent -2.42,-1.5 2.42,1.5, height 0.25
Harwin_S2751-46R [mm] "Test Point, SMT"
  rect 2.2x1.4 smd: 1(0,0)
  body extent -1,-0.6 1,0.6, height 1.4
HXB_F61 [mm] "SMD, 2-Leads, Dia 6.3mm"
  rect 3.5x1.6 smd: 1(-2.7,0) 2(2.7,0)
  silkscreen extent -3.4,-3.4 3.4,3.4, body extent -3.4,-3.4 3.4,3.4, height 6.11
IEC_HighVoltage_Small [mil]
  silkscreen extent -107,-88 107,97
IEC_HotSurface_Small [mil]
  silkscreen extent -107,-93 107,92
Keystone5005 [mil] "Keystone Compact loops"
  round 87 hole 63: 1(0,0)
  silkscreen extent -70,-70 70,70, body extent -63,-63 62,63, height 225
Keystone5006 [mil] "Keystone Compact loops"
  round 87 hole 63: 1(0,0)
  silkscreen extent -70,-70 70,70, body extent -63,-63 62,63, height 225
Keystone5007 [mil] "Keystone Compact loops"
  round 87 hole 63: 1(0,0)
  silkscreen extent -70,-70 70,70, body extent -63,-63 62,63, height 225
"LS L29K_Red" [mm] "SMD, 2-Leads, Body 1.3x0.8mm"
  rect 0.8x0.8 smd paste-0.4: 1(-0.75,0) 2(0.75,0)
  silkscreen extent -0.1,-0.5 1.45,0.5, body extent -0.9,-0.45 0.9,0.45, height 0.67
Molex_0395443002 [mm] "Terminal Block, 5.08mm, 2x1, TH"
  rect 2.15x2.15 hole 1.65: 1(-2.54,0)
  round 2.15 hole 1.65: 2(2.54,0)
  silkscreen extent -5.4,-4.83 5.08,5.08, body extent -5.08,-4.83 5.08,5.08, height 14.48
RQS0052A-MFG [mm]
  rrect10% 1.05x1.05 smd paste+0 mask+0: 1(-5.675,5.2) 16(-5.675,-5.2) 27(5.675,-5.2) 42(5.675,5.2)
  rrect25% 1.05x0.4 smd paste+0 mask+0: 2(-5.675,4.225) 3(-5.675,3.575) 4(-5.675,2.925) 5(-5.675,2.275) 6(-5.675,1.625) 7(-5.675,0.975) 8(-5.675,0.325) 9(-5.675,-0.325) 10(-5.675,-0.975) 11(-5.675,-1.625) 12(-5.675,-2.275) 13(-5.675,-2.925) 14(-5.675,-3.575) 15(-5.675,-4.225) 28(5.675,-4.225) 29(5.675,-3.575) 30(5.675,-2.925) 31(5.675,-2.275) 32(5.675,-1.625) 33(5.675,-0.975) 34(5.675,-0.325) 35(5.675,0.325) 36(5.675,0.975) 37(5.675,1.625) 38(5.675,2.275) 39(5.675,2.925) 40(5.675,3.575) 41(5.675,4.225)
  rrect25% 0.4x1.05 smd paste+0 mask+0: 17(-1.935,-5.675) 18(-1.285,-5.675) 19(-0.635,-5.675) 20(0.015,-5.675) 21(0.665,-5.675) 22(1.315,-5.675) 23(1.965,-5.675) 24(2.615,-5.675) 25(3.265,-5.675) 26(3.915,-5.675) 43(3.915,5.675) 44(3.265,5.675) 45(2.615,5.675) 46(1.965,5.675) 47(1.315,5.675) 48(0.665,5.675) 49(0.015,5.675) 50(-0.635,5.675) 51(-1.285,5.675) 52(-1.935,5.675)
  silkscreen extent -6.88,-6.05 4.77,6.05, body extent -6,-6 6,6, height 1
SML-E1_Yellow [mm] "SMD, 2-Leads, Body 1.6x0.8mm"
  rect 0.8x0.8 smd: 1(0.825,0) 2(-0.825,0)
  silkscreen extent -1.8,-0.8 1.3,0.8, body extent -0.85,-0.45 0.85,0.45, height 0.46
SNT-100-BK-G [mil] "Samtec STEP model"
  round 1 on Mech3: 0(0,0)
  body extent -100,-50 100,50, height 344
SOD-123 [mm] "On Semi recommended land pattern"
  rect 0.915x1.22 smd: 1(-1.637,0) 2(1.637,0)
  silkscreen extent -2.74,-1.17 2.03,1.16, body extent -1.93,-0.9 1.93,0.9, height 1.35
SOD-323 [mm] "NXP recommended land pattern"
  rect 0.6x0.6 smd paste-0.05: 1(-1.1,0) 2(1.1,0)
  silkscreen extent -2.06,-0.87 1.53,0.86, body extent -1.3,-0.67 1.3,0.68, height 1.1
TEC_282834-2 [mm] "TEC"
  rect 1.6x1.6 hole 1.1: 1(-1.27,0)
  round 1.6 hole 1.1: 2(1.27,0)
  silkscreen extent -3.66,-3.4 2.9,3.4, body extent -2.77,-3.25 2.77,3.25, height 10.01
Testpoint_Keystone_Compact [mil] "Compact SMT test point"
  rrect10% 275x175 smd: 1(0,0)
  silkscreen extent -110,-80 110,80, body extent -75,-56 75,56, height 91
TI_Stacked_Overlay_Small [mil]
  silkscreen extent -418,-98 418,98
TRIM_3224X [mm] "Bourns"
  rect 1.9x1.3 smd: 1(-2.55,1.25) 3(-2.55,-1.25)
  rect 1.9x2 smd: 2(2.55,0)
  silkscreen extent -1.9,-2.5 1.9,2.5, body extent -1.8,-2.4 1.8,2.4, height 5.31
TSW-102-07-G-S [mm] "Samtec 100mil, 1x2, 230 mil above insulator"
  rrect50% 1.65x1.65 hole 1.016: 1(-1.27,0)
  round 1.65 hole 1.016: 2(1.27,0)
  body extent -2.54,-1.27 2.54,1.27, height 8.38
TSW-103-07-G-S [mm] "Samtec 100mil, 1x3, 230 mil above insulator"
  rrect50% 1.65x1.65 hole 1.016: 1(-2.54,0)
  round 1.65 hole 1.016: 2(0,0) 3(2.54,0)
  body extent -3.81,-1.27 3.81,1.27, height 8.38
WEEE_Minimum [mil] "WEEElie bin"
  silkscreen extent -95,-172 99,104

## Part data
15VIN 15VINF ISO15VH ISO15VL: library part CMP-0055142-2, "Test Point, Compact, Red, TH", Color=Red, Manufacturer="Keystone Electronics", Supplier Part Number 1=36-5005-ND
C1 C11: library part CMP-0750154-1, "CAP, CERM, 10 µF, 25 V,+/- 10%, X7R, AEC-Q200 Grade 1, 1206", Cap_Case=1206, Manufacturer="Taiyo Yuden", TempCo=X7R, Tolerance_%=10%, Value2=25V, ValueDisplayed=10µF
C2 C12: library part CMP-0078265-1, "CAP, CERM, 0.22 µF, 16 V,+/- 10%, X7R, AEC-Q200 Grade 1, 0402", Cap_Case=0402, Manufacturer=MuRata, Supplier Part Number 1=490-10671-1-ND, TempCo=X7R, Tolerance_%=10%, Value2=16V, ValueDisplayed=0.22µF
C3 C13: library part CMP-0007975-2, "CAP, CERM, 2.2 uF, 25 V, +/- 10%, X7R, AEC-Q200 Grade 1, 0805", Cap_Case=0805, Manufacturer=TDK, Supplier Part Number 1=445-6965-1-ND, TempCo=X7R, Tolerance_%=10%, Value1=Unknown, Value2=25V, ValueDisplayed=2.2uF
C5 C23: library part CMP-0006348-2, "CAP, CERM, 22 pF, 50 V, +/- 5%, C0G/NP0, AEC-Q200 Grade 1, 0402", Cap_Case=0402, Manufacturer=MuRata, Supplier Part Number 1=490-9648-1-ND, TempCo=C0G/NP0, Tolerance_%=5%, Value1=Unknown, Value2=50V, ValueDisplayed=22pF
C6 C14: library part CMP-0006251-2, "CAP, CERM, 68 pF, 50 V, +/- 5%, C0G/NP0, 0402", Alternate Manufacturer=Murata, Alternate PartNumber=GRM1555C1H680JA01D, Cap_Case=0402, Manufacturer=TDK, Supplier Part Number 1=445-1245-1-ND, TempCo=C0G/NP0, Tolerance_%=5%, Value1=Unknown, Value2=50V, ValueDisplayed=68pF
C7 C58: library part CMP-0007877-2, "CAP, CERM, 2.2 uF, 50 V, +/- 10%, X7R, 0805", Cap_Case=0805, Manufacturer=TDK, Supplier Part Number 1=445-5968-1-ND, TempCo=X7R, Tolerance_%=10%, Value1="0.00366 ohm", Value2=50V, ValueDisplayed=2.2uF
C8 C36 C59 C69: library part CMP-0075366-3, "CAP, CERM, 2.2 µF, 25 V,+/- 10%, X7S, 0603", Cap_Case=0603, Manufacturer=MuRata, Supplier Part Number 1=490-12732-1-ND, TempCo=X7S, Tolerance_%=10%, Value2=25V, ValueDisplayed=2.2µF
C9 C26: library part CMP-0750099-1, "CAP, CERM, 1 µF, 35 V,+/- 10%, X5R, AEC-Q200 Grade 3, 0402", Cap_Case=0402, Manufacturer=MuRata, TempCo=X5R, Tolerance_%=10%, Value2=35V, ValueDisplayed=1µF
C10 C27: library part CMP-0006356-2, "CAP, CERM, 0.1 uF, 50 V, +/- 10%, X7R, AEC-Q200 Grade 1, 0402", Cap_Case=0402, Manufacturer=MuRata, Supplier Part Number 1=490-10672-1-ND, TempCo=X7R, Tolerance_%=10%, Value1=Unknown, Value2=50V, ValueDisplayed=0.1uF
C15 C16 C17 C18: library part CMP-0084048-1, "CAP, CERM, 0.022 µF, 1000 V,+/- 10%, X7R, AEC-Q200 Grade 1, 1206", Cap_Case=1206, Manufacturer=Kemet, TempCo=X7R, Tolerance_%=10%, Value2=1000V, ValueDisplayed=0.022µF
C19 C20 C21 C38: library part CMP-0009326-2, "CAP, CERM, 0.1 uF, 1000 V, +/- 10%, X7R, 1812", Cap_Case=1812, Manufacturer=Kemet, Supplier Part Number 1=399-6523-1-ND, TempCo=X7R, Tolerance_%=10%, Value1=Unknown, Value2=1000V, ValueDisplayed=0.1uF
C22 C35 C60 C68: library part CMP-0093289-1, "0.056 µF ±10% 50V Ceramic Capacitor X7R 0603 (1608 Metric)", Digikey Part Number=399-20502-1-ND, Manufacturer=KEMET, Mouser Part Number=80-C0603X563K5RAUTO, Operating Temperature Range="-55°C to +125°C", TempCo=15%, Temperature Characteristic=X7R, Tolerance_%=10%, ValueDisplayed=0.056uF
C24: library part CMP-0750159-1, "CAP, AL, 47 µF, 25 V, +/- 20%, 0.05 ohm, AEC-Q200 Grade 1, SMD", Cap_Case=6.3x5.8mm, Manufacturer=Chemi-Con, Tolerance_%=20%, Value1="0.05 ohm", Value2=25V, ValueDisplayed=47µF
C25: library part CMP-0081062-1, "CAP, CERM, 10 µF, 25 V,+/- 5%, X7R, AEC-Q200 Grade 1, 1206", Cap_Case=1206_180, Manufacturer=Kemet, Supplier Part Number 1=399-15734-1-ND, TempCo=X7R, Tolerance_%=5%, Value2=25V, ValueDisplayed=10µF
C28 C61: library part CMP-0009163-2, "CAP, CERM, 4.7 uF, 50 V, +/- 20%, X7R, AEC-Q200 Grade 1, 1210", Cap_Case=1210, Manufacturer=TDK, Supplier Part Number 1=445-13030-1-ND, TempCo=X7R, Tolerance_%=20%, Value1=Unknown, Value2=50V, ValueDisplayed=4.7uF
C29 C32 C47 C53 C62 C65: library part CMP-0079911-1, "CAP, CERM, 0.1 µF, 50 V,+/- 10%, X8R, AEC-Q200 Grade 0, 0603", Cap_Case=0603, Manufacturer=TDK, Supplier Part Number 1=445-173697-1-ND, TempCo=X8R, Tolerance_%=10%, Value2=50V, ValueDisplayed=0.1µF
C30 C31 C63 C64: library part CMP-0091069-1, "Cap Ceramic 10uF 25V X7S 10% Pad SMD 0805 +125°C Automotive T/R", Manufacturer="TDK Corporation", Operating Temperature Range="-55°C to +125°C", TempCo=22%, Temperature Characteristic=X7S, Tolerance_%=0.1%, ValueDisplayed=10uF
C33 C66: library part CMP-0085950-1, "CAP, CERM, 10 µF, 50 V,+/- 10%, X7R, AEC-Q200 Grade 1, 1206", Cap_Case=1206, Manufacturer=TDK, TempCo=X7R, Tolerance_%=10%, Value2=50V, ValueDisplayed=10µF
C34 C67: library part CMP-0083707-1, "CAP, CERM, 1 µF, 50 V,+/- 20%, X5R, AEC-Q200 Grade 3, 0603", Cap_Case=0603, Manufacturer=TDK, Supplier Part Number 1=445-12510-1-ND, TempCo=X5R, Tolerance_%=20%, Value2=50V, ValueDisplayed=1µF
C39 C40 C56 C57: library part CMP-0860835-1, "CAP, CERM, 43 pF, 50 V,+/- 5%, C0G/NP0, AEC-Q200 Grade 1, 0402", Cap_Case=0402, Manufacturer=MuRata, TempCo=C0G/NP0, Tolerance_%=5%, Value2=50V, ValueDisplayed=43pF
C41 C44: library part CMP-0082523-1, "CAP, CERM, 1 µF, 25 V,+/- 10%, X7R, AEC-Q200 Grade 1, 0603", Cap_Case=0603, Manufacturer=TDK, Supplier Part Number 1=445-9819-1-ND, TempCo=X7R, Tolerance_%=10%, Value2=25V, ValueDisplayed=1µF
C42: library part CMP-0006308-2, "CAP, CERM, 100 pF, 50 V, +/- 5%, C0G/NP0, AEC-Q200 Grade 1, 0402", Cap_Case=0402, Manufacturer=TDK, Supplier Part Number 1=445-5596-1-ND, TempCo=C0G/NP0, Tolerance_%=5%, Value1=Unknown, Value2=50V, ValueDisplayed=100pF
C43: library part CMP-0006308-1, "CAP, CERM, 100 pF, 50 V, +/- 5%, C0G/NP0, AEC-Q200 Grade 1, 0402", Cap_Case=0402, Manufacturer=TDK, Supplier Part Number 1=445-5596-1-ND, TempCo=C0G/NP0, Tolerance_%=5%, Value1=Unknown, Value2=50V, ValueDisplayed=100pF
C45 C46 C50 C51 C52 C55: library part CMP-0007214-4, "CAP, CERM, 39 pF, 50 V, +/- 5%, C0G/NP0, 0603", Cap_Case=0603, Manufacturer=MuRata, Supplier Part Number 1=490-1417-1-ND, TempCo=C0G/NP0, Tolerance_%=5%, Value1=Unknown, Value2=50V, ValueDisplayed=39pF
C48: library part CMP-0084059-1, "CAP, CERM, 22 µF, 25 V,+/- 10%, X5R, AEC-Q200 Grade 3, 1210", Cap_Case=1210, Manufacturer=MuRata, TempCo=X5R, Tolerance_%=10%, Value2=25V, ValueDisplayed=22µF
C49: library part CMP-0064919-2, "CAP, CERM, 1 uF, 630 V,+/- 10%, X7R, AEC-Q200 Grade 1, 2220", Cap_Case=2220, Manufacturer="Knowles Capacitors", PartNumber=2220Y6300105KXTWS2, Supplier Part Number 1=1608-1181-1-ND, TempCo=X7R, Tolerance_%=10%, Value1=Unknown, Value2=630V, ValueDisplayed=1uF
C54: library part CMP-0089980-1, "10µF ±10% 50V Ceramic Capacitor X7R 1210 (3225 Metric)", Digikey Part Number=587-6160-1-ND, Manufacturer="Taiyo Yuden", Mouser Part Number=963-UMK325AB7106KMHP, Operating Temperature Range="-55°C to +125°C", TempCo=15%, Temperature Characteristic=X7R, Tolerance_%=10%, ValueDisplayed=10uF
D1 D3 D4 D6: library part CMP-0090564-1, "Diode Schottky 40V 500mA Surface Mount SOD-123", Digikey Part Number=NRVB0540T1GOSCT-ND, Forward Current=0.5A, Manufacturer="On Semiconductor", Max Surge Forward Current=5.5A, Mouser Part Number=863-NRVB0540T1G, Operating Temperature Range="-55°C to +150°C", Peak Reverse Current=20uA
D2 D5: library part CMP-0084402-3, "Diode, Zener, 18 V, 500 mW, AEC-Q101, SOD-123", Manufacturer="Diodes Inc.", Power_W=500mW, Value1=0.5W
D11 D12: library part CMP-0028447-2, "Diode, Schottky, 30 V, 0.2 A, SOD-323", Manufacturer="Diodes Inc.", Value1=0.2A, Value2=1V
GND_LV GNDHV GNDLV GNDLVF ISO15VGND ISO15VSW: library part CMP-0055143-1, "Test Point, Compact, Black, TH", Color=Black, Manufacturer=Keystone, Supplier Part Number 1=36-5006-ND
HS_FLT LDO LS_FLT: library part CMP-0002902-2, "LED, Red, SMD", Color=Red, Manufacturer=OSRAM, Value1=W, Value2=1.8V
HS_OC LS_OC: library part CMP-0002977-1, "LED, Yellow, SMD", Color=yellow, Manufacturer=Rohm, Power_TotalModule=54mW, Supplier Part Number 1=511-1588-1-ND, Value1=0.054W, Value2=2.2V
HVIN LDO5V: library part CMP-0055142-1, "Test Point, Compact, Red, TH", Color=Red, Manufacturer=Keystone, Supplier Part Number 1=36-5005-ND
J1 J4: library part CMP-0095823-1, "Connector BNC Female 0Hz To 2GHz 50 Ohm Solder Right Angle Through Hole Gold Tray", Dielectric Material=Polypropylene, Digikey Part Number=WM5514-ND, Frequency_Fixed=2GHz, Manufacturer=Molex, Mouser Part Number=538-73137-5003, Operating Temperature Range=to, Voltage_V=500V
J2 J3: library part CMP-0075407-2, "Header, 100mil, 3x1, Gold, TH", Color=Black, Current_A=6.3A, Manufacturer=Samtec, Supplier Part Number 1=SAM1029-03-ND, Voltage_V=550V
J5: library part CMP-0055342-2, "Terminal Block, 5.08mm, 2x1, TH", Color=Black, Current_A=15A, Manufacturer=Molex, Supplier Part Number 1=WM7853-ND, Voltage_V=300V
J6: library part CMP-0054974-1, "Terminal Block, 2x1, 2.54mm, TH", Manufacturer="TE Connectivity", Supplier Part Number 1=A98333-ND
